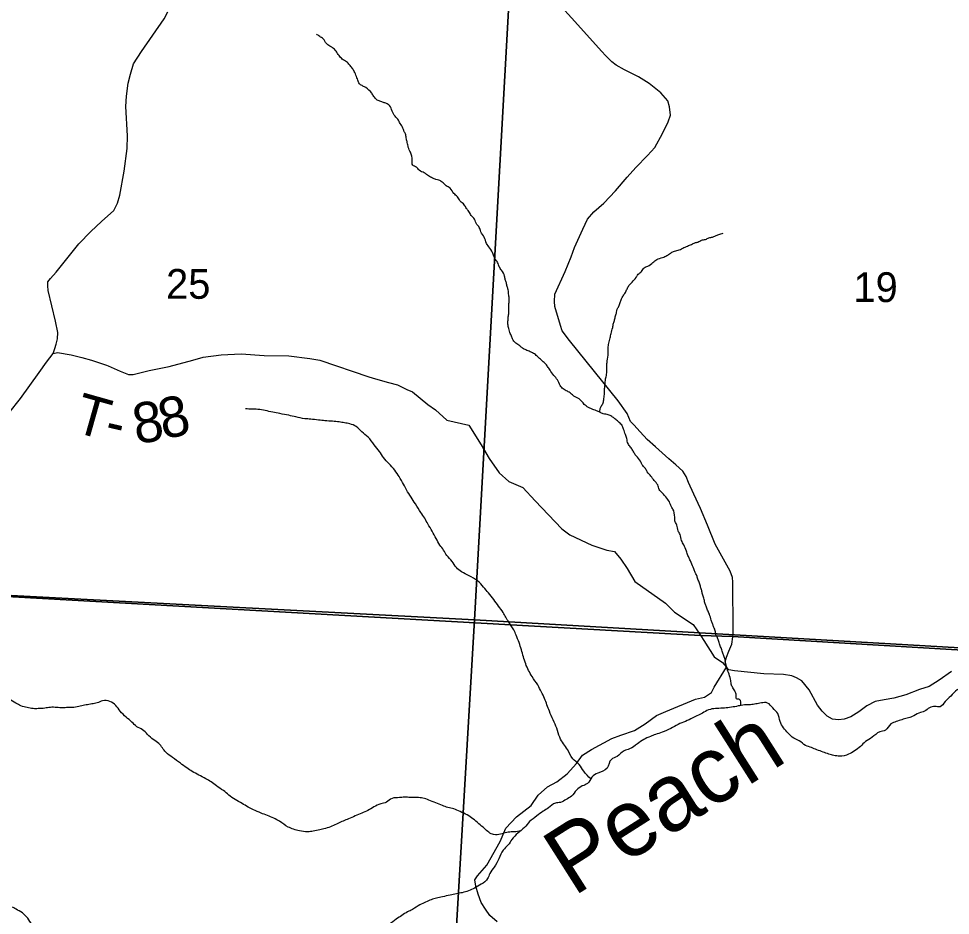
# Model space of a CAD drawing. Extents: x -20.2 to 34, y 0 to 22.
# Drawn here: x 3.126 to 4.435, y 18.737 to 19.997 of the extents above; entities that cross this region are included whole.
import ezdxf

# ---------------------------------------------------------------- set-up
doc = ezdxf.new("R2010")
doc.units = 0
for name, color, linetype in [('Default', 7, 'Continuous'), ('GM_X_County_Road', 7, 'Continuous'), ('GM_X_Minor_River', 7, 'Continuous'), ('GM_X_Minor_River_Text', 7, 'Continuous'), ('GM_X_Section', 7, 'Continuous'), ('GM_X_Section_Text', 7, 'Continuous'), ('GM_X_Township_Road', 7, 'Continuous'), ('GM_X_Township_Road_Text', 7, 'Continuous')]:
    doc.layers.add(name, color=color, linetype=linetype)

msp = doc.modelspace()

# ---------------------------------------------------------------- linework, layer by layer
at = {"layer": 'Default'}
msp.add_lwpolyline([(8.1508, 20.9), (2.1, 20.9), (2.1, 19.2514), (2.9253, 19.1951), (4.084, 19.1299), (4.129, 19.1285), (4.5, 19.1063), (4.5753, 19.1032), (5.0716, 19.0751), (5.6168, 19.0426), (5.628, 19.0419), (5.9006, 19.026), (6.5332, 18.9927), (7.3871, 18.9465), (7.5395, 18.9382), (7.8072, 18.9199), (8.043, 18.9097), (8.0485, 19.0914), (8.0709, 19.4522), (8.1316, 20.5548)], close=True, dxfattribs=at)
msp.add_lwpolyline([(4.5, 19.1063), (4.129, 19.1285), (4.084, 19.1299), (2.9253, 19.1951), (2.1, 19.2514), (2.1, 14.1), (5.3953, 14.1)], dxfattribs=at)
at = {"layer": 'GM_X_County_Road'}
for points in [[(4.1298, 19.1407), (4.1298, 19.1465), (4.1294, 19.1947), (4.1294, 19.205), (4.1287, 19.2116), (4.1255, 19.2205), (4.1043, 19.2583), (4.0936, 19.2849), (4.0839, 19.3083), (4.0747, 19.3284), (4.0672, 19.3448), (4.0638, 19.3532), (4.059, 19.3607), (4.049, 19.3698), (4.0392, 19.3782), (4.0206, 19.3951), (4.009, 19.4055), (3.9989, 19.416), (3.9901, 19.4258), (3.9856, 19.4307), (3.981, 19.442), (3.968, 19.4595), (3.9234, 19.5153), (3.8999, 19.5444), (3.8897, 19.5579), (3.8872, 19.5654), (3.8792, 19.5922), (3.8785, 19.5995), (3.8792, 19.6095), (3.8938, 19.6416), (3.902, 19.6619), (3.9067, 19.6751), (3.9183, 19.7008), (3.9253, 19.715), (3.9338, 19.7254), (3.9482, 19.7375), (3.9646, 19.7548), (3.9807, 19.7741), (3.9932, 19.7876), (4.0096, 19.8043), (4.0197, 19.8156), (4.0306, 19.8356), (4.0386, 19.8518), (4.0417, 19.8613), (4.0404, 19.8729), (4.0379, 19.8811), (4.0283, 19.8925), (4.0117, 19.9057), (3.9969, 19.915), (3.9773, 19.9248), (3.9652, 19.9312), (3.9593, 19.936), (3.9509, 19.9444), (3.9448, 19.9512), (3.9072, 19.9927), (3.8833, 20.0191)], [(4.1205, 19.0855), (4.1185, 19.093), (4.1206, 19.0996), (4.1239, 19.1078), (4.1278, 19.1178), (4.1292, 19.1279), (4.1296, 19.131), (4.1298, 19.1407)], [(4.4365, 19.0795), (4.4194, 19.067), (4.4051, 19.0584), (4.3914, 19.0538), (4.3725, 19.0463), (4.3557, 19.042), (4.342, 19.0395), (4.3293, 19.037), (4.3177, 19.0308), (4.3063, 19.0226), (4.2951, 19.0156), (4.2858, 19.0124), (4.2778, 19.0113), (4.2694, 19.0124), (4.2617, 19.0167), (4.2548, 19.0233), (4.2485, 19.032), (4.2366, 19.0534), (4.2263, 19.0663), (4.2189, 19.0705), (4.212, 19.0732), (4.2006, 19.075), (4.1729, 19.0761), (4.1316, 19.0801), (4.1237, 19.0818), (4.1205, 19.0855)]]:
    msp.add_lwpolyline(points, dxfattribs=at)
at = {"layer": 'GM_X_Minor_River'}
for points in [[(3.8204, 19.5447), (3.8189, 19.5493), (3.8166, 19.5542), (3.8144, 19.5611), (3.8133, 19.5676), (3.8134, 19.5732), (3.8138, 19.5778), (3.8146, 19.5835), (3.8146, 19.5918), (3.8147, 19.5964), (3.8151, 19.6025), (3.8144, 19.6082), (3.8137, 19.6158), (3.8122, 19.6203), (3.8111, 19.6253), (3.8096, 19.6302), (3.8085, 19.6348), (3.8044, 19.6432), (3.801, 19.6481), (3.7988, 19.6539), (3.795, 19.66), (3.7924, 19.6657), (3.7879, 19.6744), (3.783, 19.6809), (3.7801, 19.6897), (3.7752, 19.6973), (3.773, 19.7034), (3.7696, 19.7076), (3.7662, 19.7149), (3.7617, 19.7202), (3.7583, 19.7259), (3.755, 19.7301), (3.752, 19.7351), (3.7463, 19.7405), (3.7422, 19.7466), (3.7373, 19.7512), (3.732, 19.7584), (3.7264, 19.7619), (3.7207, 19.7672), (3.7162, 19.7699), (3.712, 19.7707), (3.7075, 19.7727), (3.7018, 19.7757), (3.6958, 19.78), (3.6886, 19.7838), (3.6848, 19.788), (3.6795, 19.7907), (3.6788, 19.7979), (3.6762, 19.809), (3.6733, 19.8162), (3.6718, 19.8227), (3.6707, 19.8276), (3.6696, 19.8337), (3.6677, 19.8379), (3.6651, 19.8444), (3.661, 19.8509), (3.6588, 19.8554), (3.6546, 19.8596), (3.6468, 19.8745), (3.6426, 19.8776), (3.6384, 19.8788), (3.6335, 19.8807), (3.6286, 19.883), (3.6248, 19.8876), (3.6218, 19.8922), (3.6135, 19.8998), (3.6094, 19.9021), (3.6052, 19.9045), (3.603, 19.9087), (3.6004, 19.9155), (3.5974, 19.9227), (3.5944, 19.9273), (3.5906, 19.9319), (3.5865, 19.9361), (3.5805, 19.94), (3.5759, 19.9449), (3.5718, 19.951), (3.5669, 19.956), (3.5628, 19.9583), (3.5582, 19.9618), (3.5537, 19.9686), (3.5488, 19.9717), (3.5443, 19.9752)], [(3.9422, 19.4438), (3.9437, 19.4507), (3.9464, 19.4556), (3.948, 19.4609), (3.9488, 19.4685), (3.9492, 19.4727), (3.9492, 19.4769), (3.9497, 19.4822), (3.9505, 19.4905), (3.952, 19.4966), (3.9521, 19.5076), (3.9526, 19.5137), (3.9533, 19.5182), (3.9542, 19.5296), (3.9542, 19.5338), (3.955, 19.5406), (3.957, 19.5482), (3.9582, 19.5543), (3.9605, 19.5626), (3.9617, 19.5687), (3.9632, 19.5736), (3.9644, 19.5793), (3.966, 19.5842), (3.9668, 19.5884), (3.9691, 19.5925), (3.971, 19.5978), (3.9729, 19.6028), (3.9753, 19.6073), (3.9783, 19.6118), (3.9806, 19.6167), (3.9833, 19.6217), (3.9879, 19.6266), (3.9933, 19.633), (3.9964, 19.6375), (4.0009, 19.6413), (4.0048, 19.6466), (4.0097, 19.6488), (4.017, 19.6541), (4.0223, 19.6582), (4.0307, 19.6612), (4.0364, 19.6638), (4.0417, 19.6672), (4.0459, 19.6694), (4.0524, 19.6712), (4.0589, 19.6742), (4.0657, 19.6772), (4.0714, 19.6795), (4.076, 19.6817), (4.0802, 19.6828), (4.0855, 19.6854), (4.0908, 19.6865), (4.0958, 19.6888), (4.1007, 19.6899), (4.1049, 19.6917), (4.1095, 19.6932), (4.1156, 19.6954)], [(4.1405, 19.0314), (4.1387, 19.0399), (4.1346, 19.041), (4.1339, 19.046), (4.1328, 19.0509), (4.1294, 19.0563), (4.1271, 19.0616), (4.1261, 19.0685), (4.1231, 19.078), (4.1209, 19.0848), (4.1172, 19.1), (4.1153, 19.105), (4.1135, 19.1111), (4.1109, 19.1168), (4.1094, 19.1229), (4.1071, 19.1278), (4.1053, 19.1324), (4.1042, 19.1377), (4.1023, 19.1423), (4.1008, 19.1465), (4.099, 19.1514), (4.0964, 19.1598), (4.0938, 19.1655), (4.0919, 19.1709), (4.09, 19.1758), (4.0886, 19.1823), (4.0867, 19.188), (4.0856, 19.1929), (4.0841, 19.1979), (4.0827, 19.2036), (4.0801, 19.2089), (4.0786, 19.2143), (4.0763, 19.2184), (4.0745, 19.2234), (4.0707, 19.2325), (4.0685, 19.2375), (4.0663, 19.2421), (4.064, 19.2485), (4.0603, 19.2573), (4.0573, 19.2634), (4.0551, 19.2718), (4.0525, 19.2771), (4.0506, 19.2851), (4.0484, 19.2897), (4.0477, 19.2961), (4.0451, 19.3075), (4.0425, 19.3117), (4.041, 19.3159), (4.0365, 19.3228), (4.0301, 19.3304), (4.026, 19.335), (4.0237, 19.3415), (4.0189, 19.3476), (4.0143, 19.3537), (4.0091, 19.3598), (4.0065, 19.3644), (4.0027, 19.3686), (4.0005, 19.3728), (3.9952, 19.3805), (3.9914, 19.385), (3.9888, 19.39), (3.9854, 19.3946), (3.9821, 19.3995), (3.9802, 19.4068), (3.9784, 19.4125), (3.9758, 19.4197), (3.9731, 19.4258), (3.9682, 19.4304), (3.9637, 19.4342), (3.9592, 19.4377), (3.9543, 19.44), (3.9471, 19.4416), (3.9429, 19.4435), (3.9376, 19.4458), (3.9308, 19.4482), (3.9263, 19.4505), (3.9206, 19.4547), (3.9135, 19.4624), (3.9059, 19.4662), (3.9018, 19.47), (3.8968, 19.4731), (3.8908, 19.4766), (3.8867, 19.4812), (3.8829, 19.4892), (3.8777, 19.4953), (3.8724, 19.5029), (3.869, 19.5079), (3.8656, 19.5121), (3.86, 19.5171), (3.8555, 19.5213), (3.8506, 19.5255), (3.8445, 19.5286), (3.8385, 19.5313), (3.8339, 19.5336), (3.8298, 19.537), (3.8245, 19.5409), (3.8204, 19.5447)], [(3.9296, 18.9285), (3.9198, 18.9391), (3.9134, 18.9486), (3.9044, 18.9567), (3.8969, 18.9696), (3.8913, 18.9776), (3.886, 18.9868), (3.8819, 18.9994), (3.8767, 19.0112), (3.8715, 19.0234), (3.8681, 19.0325), (3.8648, 19.0413), (3.8603, 19.0504), (3.8551, 19.0603), (3.8472, 19.0721), (3.8423, 19.0809), (3.8382, 19.0901), (3.8323, 19.1099), (3.8289, 19.1198), (3.8249, 19.1304), (3.8215, 19.1377), (3.8144, 19.1487), (3.8065, 19.1621), (3.8001, 19.1712), (3.7933, 19.1804), (3.7858, 19.1896), (3.7791, 19.198), (3.7704, 19.2068), (3.7587, 19.2137), (3.7481, 19.2195), (3.7409, 19.2252), (3.7349, 19.234), (3.7274, 19.2424), (3.7229, 19.2497), (3.7177, 19.2569), (3.7124, 19.2661), (3.7068, 19.2764), (3.7008, 19.2867), (3.6963, 19.2947), (3.6911, 19.3027), (3.6832, 19.3149), (3.6772, 19.3245), (3.6708, 19.3344), (3.6667, 19.3424), (3.6603, 19.3531), (3.6543, 19.3622), (3.646, 19.3714), (3.6385, 19.3798), (3.6329, 19.3886), (3.6254, 19.3978), (3.6167, 19.4088), (3.608, 19.4161), (3.6001, 19.4234), (3.591, 19.4273), (3.5835, 19.4288), (3.5759, 19.43), (3.5668, 19.4309), (3.5562, 19.4317), (3.5471, 19.4326), (3.5361, 19.4338), (3.5277, 19.4346), (3.5152, 19.437), (3.5054, 19.4393), (3.4929, 19.4417), (3.4827, 19.4437), (3.4618, 19.4476), (3.4535, 19.4481), (3.4447, 19.4482)], [(4.7373, 18.9945), (4.7368, 18.9965), (4.7292, 18.9946), (4.7186, 18.9997), (4.7088, 19.0028), (4.6994, 19.0089), (4.6891, 19.0132), (4.6808, 19.0178), (4.6737, 19.022), (4.665, 19.0259), (4.6566, 19.0309), (4.6483, 19.0378), (4.6351, 19.0428), (4.6279, 19.0452), (4.6177, 19.0475), (4.6078, 19.0495), (4.6003, 19.0518), (4.5927, 19.0538), (4.5851, 19.0565), (4.5775, 19.0585), (4.5703, 19.0608), (4.5609, 19.0635), (4.5495, 19.0667), (4.5378, 19.069), (4.5287, 19.0699), (4.5203, 19.0696), (4.5131, 19.0692), (4.504, 19.0693), (4.4968, 19.0697), (4.4877, 19.0698), (4.4805, 19.0699), (4.4732, 19.0657), (4.4652, 19.0597), (4.4527, 19.056), (4.4447, 19.0534), (4.4355, 19.0444), (4.4275, 19.0369), (4.4206, 19.0297), (4.413, 19.0301), (4.4058, 19.0283), (4.3986, 19.0234), (4.3909, 19.0208), (4.3814, 19.016), (4.3742, 19.0137), (4.3666, 19.0115), (4.359, 19.0089), (4.3514, 19.0056), (4.3437, 18.9969), (4.3357, 18.9943), (4.325, 18.9868), (4.3159, 18.9808), (4.3086, 18.974), (4.3002, 18.9676), (4.2919, 18.9631), (4.2793, 18.9602), (4.2713, 18.9614), (4.2642, 18.9633), (4.2562, 18.9661), (4.2475, 18.9692), (4.2399, 18.9723), (4.2316, 18.9754), (4.2225, 18.9819), (4.215, 18.9854), (4.2071, 18.9926), (4.2003, 19.0003), (4.1958, 19.0091), (4.1925, 19.0201), (4.1853, 19.0281), (4.1782, 19.035), (4.1694, 19.0351), (4.1618, 19.0336), (4.1542, 19.0325), (4.1455, 19.0322), (4.1368, 19.0308), (4.1273, 19.029), (4.1174, 19.0279), (4.1072, 19.0272), (4.0977, 19.0261), (4.0885, 19.022), (4.0809, 19.0179), (4.0729, 19.0142), (4.0626, 19.009), (4.0523, 19.0049), (4.0421, 18.9992), (4.0299, 18.994), (4.0207, 18.9907), (4.0135, 18.9881), (3.9952, 18.9776), (3.9842, 18.9705), (3.9766, 18.9679), (3.9666, 18.9596), (3.9586, 18.9558), (3.9525, 18.9434), (3.9395, 18.9366), (3.9311, 18.9306), (3.925, 18.9219), (3.9178, 18.9186)], [(3.8309, 18.8552), (3.8289, 18.8547), (3.8198, 18.854), (3.8118, 18.853), (3.803, 18.8507), (3.7932, 18.8501), (3.7803, 18.8585), (3.7724, 18.8654), (3.7641, 18.8723), (3.7562, 18.8777), (3.746, 18.8823), (3.7373, 18.8862), (3.7289, 18.8882), (3.7214, 18.8909), (3.7119, 18.8947), (3.7021, 18.8986), (3.6937, 18.9013), (3.6858, 18.9022), (3.6759, 18.9022), (3.668, 18.9027), (3.6607, 18.902), (3.6505, 18.9009), (3.6425, 18.8957), (3.6345, 18.8931), (3.625, 18.889), (3.6166, 18.8841), (3.6078, 18.8804), (3.5987, 18.8763), (3.5892, 18.8722), (3.5743, 18.8658), (3.566, 18.8621), (3.5568, 18.8587), (3.5488, 18.8569), (3.5397, 18.8547), (3.5318, 18.854), (3.5204, 18.8552), (3.512, 18.8576), (3.5045, 18.8607), (3.4924, 18.8687), (3.4841, 18.873), (3.4754, 18.8768), (3.4663, 18.8803), (3.4557, 18.885), (3.4482, 18.8888), (3.4398, 18.8938), (3.43, 18.8992), (3.421, 18.9057), (3.4134, 18.9119), (3.4036, 18.9184), (3.3961, 18.9242), (3.3889, 18.9284), (3.3787, 18.9338), (3.3696, 18.9388), (3.3621, 18.9438), (3.353, 18.9503), (3.3421, 18.9584), (3.3326, 18.9657), (3.3228, 18.9779), (3.3149, 18.9836), (3.307, 18.9909), (3.2998, 18.9974), (3.2919, 19.0017), (3.2848, 19.0082), (3.2768, 19.0151), (3.2685, 19.0235), (3.2622, 19.0315), (3.2539, 19.0373), (3.2436, 19.0381), (3.236, 19.0351), (3.2288, 19.0337), (3.2204, 19.0322), (3.2124, 19.0304), (3.2033, 19.0289), (3.1946, 19.0286), (3.1874, 19.0283), (3.1794, 19.0287), (3.1703, 19.0288), (3.1623, 19.0277), (3.1532, 19.0271), (3.146, 19.0271), (3.1377, 19.0287), (3.129, 19.031), (3.1218, 19.0349), (3.1124, 19.0403), (3.1037, 19.0453), (3.0965, 19.0503), (3.0889, 19.0553), (3.0814, 19.0584)], [(3.9178, 18.9186), (3.9097, 18.9126), (3.9025, 18.9039), (3.8952, 18.8994), (3.8872, 18.8953), (3.88, 18.8942), (3.8705, 18.8878), (3.8628, 18.8829), (3.8537, 18.8762), (3.8438, 18.8683), (3.8365, 18.86), (3.8273, 18.8521), (3.8189, 18.843), (3.8135, 18.8355), (3.8067, 18.8283), (3.8005, 18.8162), (3.794, 18.8045), (3.7878, 18.7954), (3.7847, 18.7882), (3.7759, 18.7803), (3.7664, 18.7747), (3.758, 18.771), (3.7489, 18.7684), (3.7409, 18.7669), (3.7322, 18.7651), (3.7212, 18.7625), (3.7128, 18.7607), (3.7056, 18.7585), (3.6976, 18.7551), (3.6896, 18.7514), (3.6793, 18.745), (3.6721, 18.7413), (3.6641, 18.7364), (3.6564, 18.7311), (3.6465, 18.7236), (3.6362, 18.715), (3.6278, 18.7074), (3.6201, 18.6965), (3.6105, 18.684), (3.6048, 18.6769), (3.5987, 18.6697), (3.591, 18.6618), (3.5807, 18.652), (3.5731, 18.6475), (3.5647, 18.6426), (3.5559, 18.6389), (3.5461, 18.6356), (3.5342, 18.6296), (3.5244, 18.6278), (3.5156, 18.6267), (3.5084, 18.626), (3.4997, 18.6249), (3.4906, 18.6246), (3.4799, 18.6243), (3.4712, 18.6244), (3.4617, 18.6237), (3.453, 18.6226), (3.4458, 18.6212), (3.4374, 18.6163), (3.426, 18.6114), (3.4153, 18.6092), (3.4077, 18.6093), (3.3949, 18.6132), (3.385, 18.6167), (3.3752, 18.619), (3.3649, 18.6195), (3.3577, 18.6199), (3.349, 18.6211), (3.3392, 18.6231), (3.3301, 18.6289), (3.318, 18.6332), (3.3108, 18.6363), (3.3032, 18.6401), (3.2957, 18.6443), (3.2851, 18.6516), (3.2779, 18.6536), (3.2689, 18.6586), (3.2613, 18.6632), (3.2511, 18.6682), (3.2428, 18.6717), (3.2356, 18.6744), (3.228, 18.6771), (3.2193, 18.6818), (3.2121, 18.6837), (3.203, 18.6868), (3.194, 18.6896), (3.1796, 18.6927), (3.1724, 18.6958), (3.1648, 18.7), (3.1569, 18.7039), (3.1531, 18.7111), (3.1464, 18.7211), (3.14, 18.7302), (3.1332, 18.7383), (3.1242, 18.744), (3.117, 18.7483)]]:
    msp.add_spline(points, degree=3, dxfattribs=at)
at = {"layer": 'GM_X_Section'}
for points in [[(3.8229, 20.1691), (3.7661, 19.1519), (2.7046, 19.2077), (2.7621, 20.2295)], [(3.8229, 20.1691), (4.8996, 20.1107), (4.8379, 19.0901), (3.7661, 19.1519)], [(3.7661, 19.1519), (3.7052, 18.1153), (2.6444, 18.1765), (2.7046, 19.2077)], [(4.8379, 19.0901), (4.7709, 18.0573), (3.7052, 18.1153), (3.7661, 19.1519)]]:
    msp.add_lwpolyline(points, close=True, dxfattribs=at)
at = {"layer": 'GM_X_Township_Road'}
for points in [[(3.1743, 19.5262), (3.1765, 19.5333), (3.1785, 19.5393), (3.1804, 19.5469), (3.1809, 19.5557), (3.1774, 19.5718), (3.167, 19.6149), (3.1666, 19.6215), (3.1668, 19.6269), (3.1703, 19.6318), (3.1785, 19.6405), (3.2105, 19.6804), (3.2272, 19.6978), (3.2422, 19.7116), (3.2594, 19.727), (3.2648, 19.7375), (3.2679, 19.7486), (3.274, 19.7825), (3.2784, 19.8142), (3.2786, 19.8319), (3.2763, 19.8731), (3.2771, 19.8877), (3.2798, 19.9063), (3.283, 19.9189), (3.2871, 19.9331), (3.2984, 19.9506), (3.33, 19.9966), (3.3354, 20.0064)], [(2.9153, 19.3619), (2.9171, 19.377), (2.9191, 19.3987), (2.9201, 19.4114), (2.9224, 19.4194), (2.9275, 19.4257), (2.9328, 19.4305), (2.9406, 19.4333), (2.9519, 19.4361), (2.9729, 19.4351), (3.0226, 19.4338), (3.0458, 19.4308), (3.0617, 19.4333), (3.0736, 19.4353), (3.0951, 19.4348), (3.1041, 19.4384), (3.112, 19.4421), (3.1284, 19.4631), (3.1544, 19.4994), (3.1651, 19.5138), (3.1743, 19.5262)], [(3.1743, 19.5262), (3.1803, 19.5274), (3.1996, 19.5243), (3.2147, 19.5207), (3.2282, 19.5168), (3.2491, 19.5098), (3.2513, 19.5088)], [(3.2513, 19.5088), (3.2684, 19.5015), (3.28, 19.4969), (3.2868, 19.4965), (3.309, 19.5023), (3.3372, 19.5079), (3.3707, 19.5168), (3.3852, 19.5209), (3.4103, 19.5243), (3.4383, 19.5255), (3.4708, 19.5234), (3.5052, 19.5228), (3.535, 19.5191), (3.5489, 19.517), (3.6177, 19.4934), (3.6274, 19.4905), (3.6454, 19.4853), (3.6579, 19.4822), (3.6713, 19.4758), (3.679, 19.4725), (3.7007, 19.4544), (3.7117, 19.4472), (3.7273, 19.4324), (3.7583, 19.4254), (3.7755, 19.398), (3.7871, 19.3786), (3.8009, 19.3584), (3.8145, 19.3465), (3.8341, 19.338), (3.8514, 19.319), (3.8888, 19.2798), (3.9004, 19.2713), (3.9313, 19.2568), (3.9524, 19.25), (3.963, 19.2477), (3.9717, 19.2373), (3.981, 19.2239), (3.9918, 19.2056), (4.0347, 19.1754), (4.0472, 19.1626), (4.0736, 19.1451), (4.0786, 19.1377)], [(4.0786, 19.1377), (4.0842, 19.1294), (4.0885, 19.123), (4.1031, 19.1), (4.115, 19.092), (4.1205, 19.0855)], [(3.7982, 18.7273), (3.7878, 18.7365), (3.7819, 18.7452), (3.7755, 18.7546), (3.7714, 18.7665), (3.7684, 18.7777), (3.7669, 18.7867), (3.7704, 18.7923), (3.7838, 18.8073), (3.8023, 18.8404), (3.8101, 18.859), (3.8252, 18.875), (3.8459, 18.891), (3.8557, 18.9053), (3.869, 18.9173), (3.8822, 18.9244), (3.8967, 18.9356), (3.9095, 18.9501), (3.9179, 18.9618), (3.9308, 18.9697), (3.9594, 18.9853), (3.9721, 18.9896), (3.9909, 18.9962), (4.006, 19.0059), (4.022, 19.0174), (4.0353, 19.023), (4.0767, 19.0405), (4.0897, 19.0431), (4.0994, 19.0499), (4.1032, 19.0573), (4.1205, 19.0855)]]:
    msp.add_lwpolyline(points, dxfattribs=at)

# ---------------------------------------------------------------- texts
at = {"layer": 'GM_X_Minor_River_Text'}
msp.add_text('Peach', height=0.0947, rotation=32.4326, dxfattribs=at).set_placement((3.9052, 18.7622))
at = {"layer": 'GM_X_Section_Text'}
for s, p in [('25', (3.3329, 19.6031)), ('19', (4.2988, 19.5985))]:
    msp.add_text(s, height=0.04186, rotation=0, dxfattribs=at).set_placement(p)
at = {"layer": 'GM_X_Township_Road_Text'}
for s, rotation, p in [('T', 344.2548, (3.2005, 19.4169)), ('8', 9.2896, (3.2909, 19.3986)), ('8', 12.9313, (3.3293, 19.405)), ('-', 346.8282, (3.2441, 19.4047))]:
    msp.add_text(s, height=0.0568, rotation=rotation, dxfattribs=at).set_placement(p)

doc.saveas('drawing.dxf')
